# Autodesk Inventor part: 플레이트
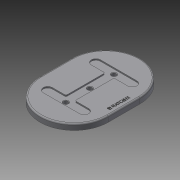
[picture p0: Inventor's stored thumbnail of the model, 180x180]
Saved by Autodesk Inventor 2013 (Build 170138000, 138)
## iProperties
Created: 2016-08
Part Number: 플레이트
Material: 알루미늄 6061
Document SubType Name: Modeling
Designer: mduedu
Density: 2.71 g/cm^3
Mass: 937.701 g
Surface Area: 657.755 cm^2
Volume: 346.015 cm^3
Author: mduedu
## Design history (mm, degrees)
sketch "스케치1" dims "d0" = 220, "d2" = 150
  geometry: L1 (35, 75)-(-35, 75); L2 (-35, 75)-(-35, -75); L3 (-35, -75)-(35, -75); L4 (35, -75)-(35, 75); L5 (35, 75)-(-35, -75); L6 (-35, 75)-(35, -75); 5 further points
  constraints: 12 end point, 5 midpoint, 2 parallel, 2 vertical alignment, 1 coincident, 1 horizontal, 1 perpendicular, 4 other
extrude "돌출1" new body sketch "스케치1" distance "d3" = 13; taper "d4" = 0 deg
sketch "스케치2"
  geometry: L1 (-63, -50)-(63, -50); L2 (63, -50)-(63, 50); L3 (63, 50)-(-63, 50); L4 (-63, 50)-(-63, -50); L5 (-63, -50)-(63, 50); L6 (63, -50)-(-63, 50); L7 (-63, 50)-(-43, 50); L8 (-43, 50)-(-43, -50); L9 (-43, -50)-(-63, -50); L10 (-63, -50)-(-63, 50); L11 (63, 50)-(43, 50); L12 (43, 50)-(43, -50); L13 (43, -50)-(63, -50); L14 (63, -50)-(63, 50); L15 (-43, -10)-(43, -10); L16 (43, -10)-(43, 10); L17 (43, 10)-(-43, 10); L18 (-43, 10)-(-43, -10); L19 (-43, -10)-(43, 10); L20 (43, -10)-(-43, 10); 1 further point
  constraints: 40 end point, 8 parallel, 4 horizontal, 4 midpoint, 4 perpendicular, 3 point on line
  dimensions: "d18" = 126 distance of L3.end L2.end; "d19" = 100 distance of L2.end L1.end; "d20" = 20 distance of L8.end L9.end; "d21" = 20 distance of L12.end L13.end (= d20); "d22" = 20 distance of L15.end L16.end
extrude "돌출3" cut sketch "스케치2" distance "d23" = 3; taper "d24" = 0 deg
fillet "모깎기2"
fillet "모깎기3"
fillet "모깎기4"
fillet "모깎기5"
fillet "모깎기6" dims "d25" = 3
sketch "스케치4"
  geometry: L1 (-43, -40)-(-43, -13) reference; L2 (-40, -10)-(40, -10) reference; L3 (43, -13)-(43, -40) reference; L4 (63, -40)-(63, 40) reference; L5 (43, 40)-(43, 13) reference; L6 (40, 10)-(-40, 10) reference; L7 (-43, 13)-(-43, 40) reference; L8 (-63, 40)-(-63, -40) reference; L9 (35, -75)-(-35, -75) reference; L10 (-35, 75)-(35, 75) reference; L11 (-53, 40)-(-53, -40); L12 (53, 40)-(53, -40); L13 (-53, 0)-(53, 0); C1 r 5 at (-53, 0); C2 r 5 at (0, 0); C3 r 5 at (53, 0); A1 r 10 centre (-53, -40) between (-63, -40) and (-43, -40) reference; A2 r 3 centre (-40, -13) between (-40, -10) and (-43, -13) reference; A3 r 3 centre (40, -13) between (43, -13) and (40, -10) reference; A4 r 10 centre (53, -40) between (43, -40) and (63, -40) reference; A5 r 10 centre (53, 40) between (63, 40) and (43, 40) reference; A6 r 3 centre (40, 13) between (40, 10) and (43, 13) reference; A7 r 3 centre (-40, 13) between (-43, 13) and (-40, 10) reference; A8 r 10 centre (-53, 40) between (-43, 40) and (-63, 40) reference; A9 r 75 centre (35, 0) between (35, -75) and (35, 75) reference; A10 r 75 centre (-35, 0) between (-35, 75) and (-35, -75) reference; 1 further point
  constraints: 6 end point, 3 centre point, 3 coincident, 2 midpoint, 1 parallel, 1 perpendicular
  dimensions: "d26" = 10 diameter of C1; "d27" = 10 diameter of C2; "d28" = 10 diameter of C3
extrude "돌출4" cut sketch "스케치4" stored distance "d29" = 3; taper "d30" = 0 deg
chamfer "모따기2" distance "d31" = 1; stored, may be unused: second distance "d32" = 2, angle "d33" = 45 deg
fillet "모깎기1" dims "d14" = 3
sketch "스케치3"
  geometry: L1 (-35, -75)-(35, -75) reference; 2 further points
  constraints: 1 vertical alignment, 1 other
  dimensions: "d15" = 12 distance from line of point (0, -63) L1
feature "엠보싱1" sketch "스케치3" dims "d0" = 220, "d2" = 150, "d16" = 0.5, "d17" = 0
node "솔리드1"
node "절단 모서리 투영1"
